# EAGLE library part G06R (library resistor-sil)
SIL RESISTOR
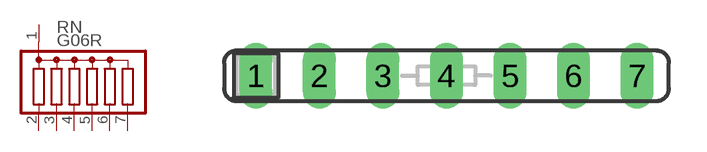
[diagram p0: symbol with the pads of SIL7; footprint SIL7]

Designator prefix RN

## G06R (OC_FARNELL: unknown; OC_NEWARK: unknown)  [SIL7]
1  1  pas
2  2  pas
3  3  pas
4  4  pas
5  5  pas
6  6  pas
7  7  pas

## Footprint SIL7 (pad centres in mm)
Single In Line
drill 0.813 long: 1 -7.62,0; 2 -5.08,0; 3 -2.54,0; 4 0,0; 5 2.54,0; 6 5.08,0; 7 7.62,0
